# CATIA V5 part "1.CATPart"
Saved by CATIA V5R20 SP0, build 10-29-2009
Part number: 1
Bounding box of the stored display mesh (mm): x -5 to 5, y -194.977 to 194.99, z -20.981 to 191.935
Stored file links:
  E:\Ehsan\Amoozesh\CATIA\CATIA Course\Advanced\Videos\Session-23\1.CATPart
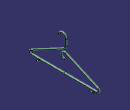
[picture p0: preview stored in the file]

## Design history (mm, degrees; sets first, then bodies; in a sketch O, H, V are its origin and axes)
AxisSystem1: origin (0, 0, 0), X (1, 0, 0), Y (0, 1, 0), Z (0, 0, 1)
Set1
  Plane1: type Normal, Curve Sketch4, RefPoint Sketch4.P3
  Sketch1 on Plane1, origin (0, 24.9565, 8.271), H (-1, 0, 0), V (0, -0.3146, 0.9492)
    circle A1 centre (0, 63.3301) radius 5
    reference projected point E1 (0, 63.3301) from Sketch4.P3
    radius A1 = 5
    concentricity: A1 E1
  Sweep1: type Unspec, Profile Sketch1, Guide Sketch4
  Sketch2 on YZ plane of AxisSystem1, origin (0, 0, 0), H (0, 1, 0), V (0, 0, 1)
    point P1 (140, 0)
    line L1 (140, 0) -> (140, -8)
    arc A1 centre (148, -8) radius 8 from (140, -8) to (154.9282, -12) ccw
    point P4 (154.9282, -12)
    distance P1 V = 140
    length L1 = 8
    radius A1 = 8
    distance P4 H = 12
    coincidence: P1 H
    vertical: L1 V
    tangency: A1 L1
  Sketch3 on XY plane of AxisSystem1, origin (0, 0, 0), H (1, 0, 0), V (0, 1, 0)
    circle A1 centre (0, 140) radius 5
    reference projected point E1 (0, 140) from Sketch2.P1
    radius A1 = 5
    concentricity: A1 E1
  Sweep2: type Unspec, Profile Sketch3, Guide Sketch2
  Fillet1: radius 2.5, on edge [face of Sweep2 | face of Sweep2]
  Symmetry1: ToTransfor Fillet1, Reference ZX plane of AxisSystem1
  Add1: tool Fillet1
  Add2: tool Sweep1
  Fillet2: radius 5, on edge [face of Sweep1 | face of Sweep1]
  Fillet3: radius 5, on edge [face of Sweep1 | face of Sweep1]
Body1 (main body)
  Sketch4 on YZ plane of AxisSystem1, origin (0, 0, 0), H (0, 1, 0), V (0, 0, 1)
    line L1 (0, 0) -> (180, 0)
    line L2 (184.0674, 19.1355) -> (6.5078, 98.1901)
    arc A1 centre (0, 83.5733) radius 16 from (6.5078, 98.1901) to (5.0334, 68.3857) ccw
    point P2 (0, 83.5733)
    point P3 (5.0334, 68.3857)
    arc A2 centre (180, 10) radius 10 from (180, 0) to (184.0674, 19.1355) ccw
    point P4 (180, 0)
    point P7 (-180, 0)
    point P8 (0, 0)
    line L3 (0, 0) -> (-180, 0)
    line L4 (-184.6886, 18.8051) -> (0, 117.0058)
    line L5 (8.4885, 131.133) -> (8.4885, 166.9459)
    arc A3 centre (-11.5115, 166.9459) radius 20 from (8.4885, 166.9459) to (-31.4646, 168.3152) ccw
    arc A4 centre (-7.5115, 131.133) radius 16 from (8.4885, 131.133) to (0, 117.0058) cw
    point P12 (0, 117.0058)
    construction line L6 (-52.2831, 168.3152) -> (29.254, 168.3152)
    point P16 (-31.4646, 168.3152)
    arc A5 centre (-180, 9.9871) radius 9.9871 from (-180, 0) to (-184.6886, 18.8051) cw
    radius A2 = 10
    length L1 = 180
    angle L2 L1 = 24
    radius A1 = 16
    radius A4 = 16
    angle L4 L3 = 28
    radius A3 = 20
    length L5 = 35.8129
    horizontal: L1 H, L6 H
    tangency: A1 L2, A2 L1, A2 L2, L5 A3, A4 L5, A4 L4, A5 L1, A5 L4
    coincidence: P2 V, P12 V, L6 P16
    symmetry: P4 P7 V, O P8 V, L1 L3 V
    vertical: L5 V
